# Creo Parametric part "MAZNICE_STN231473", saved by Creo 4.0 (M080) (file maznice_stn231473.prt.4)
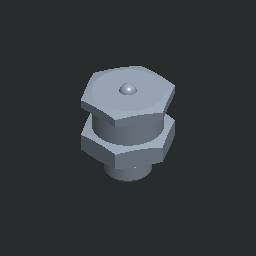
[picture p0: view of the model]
Units: millimeter Kilogram Sec (mmKs); MM, KILOGRAM, SECS
Materials in the file: OCEL_N

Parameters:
  MFG_WP_MATERIAL = "OCEL"
  NAZOV = "MAZNICE_STN231473"
  NORMA = "STN 23 1473"
  PTC_MATERIAL_NAME = "OCEL_N"

Other parameters: HMOTNOST, HUSTOTA

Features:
  1. datum plane "DTM1"
  2. cut
  3. chamfer
  4. datum plane "DTM2"
  5. datum plane "DTM3"

Other named items: THRU

Layers: 1, 2, 3, 4, 5, 6, 7, 8, 9, 10, 11, 12, 13, 14, 15, 16, 17, 18, 19, 20, 21, 22, 23, 24, 25, 26, 27, 28, 29, 30, 31, 32

Family table entries: GENERIC, MAZNICA_16_M8X1, MAZNICE_STN231473, value(d_val), value(i_val), MAZNICA_16_M10X1, MAZNICE_STN231473, MAZNICA_16_M12X1_5, MAZNICE_STN231473, # Pro/TABLE, [] S 92;, [] W 10;, [A] W  3;, [B] W 19;, [C] W 10;, [D] W 10;

Surfaces: 13 plane, 8 cylinder, 8 cone, 2 torus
